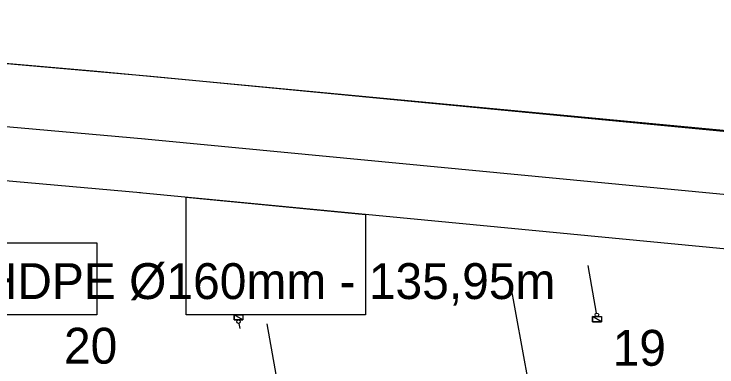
# Model space of a CAD drawing. Extents: x -263964 to -263544, y -1242317 to -1242020.
# Drawn here: x -263871.58 to -263832.36, y -1242081.29 to -1242061.62 of the extents above; entities that cross this region are included whole.
import ezdxf

# ---------------------------------------------------------------- set-up
doc = ezdxf.new("R2010")
doc.units = 0
for name, color, linetype in [('KFA_KOORDINACNA_SITUACIA_DSP_SEDA', 7, 'Continuous'), ('KFA_SO_50-2_POZIARNY_VODOVOD_BODY', 7, 'Continuous'), ('POPIS', 7, 'Continuous')]:
    doc.layers.add(name, color=color, linetype=linetype)

msp = doc.modelspace()

# ---------------------------------------------------------------- linework, layer by layer
at = {"layer": 'KFA_KOORDINACNA_SITUACIA_DSP_SEDA'}
for p, q in [((-263866.964, -1242064.823), (-263895.455, -1242062.322)), ((-263816.79, -1242069.539), (-263866.964, -1242064.823)), ((-263765.318, -1242074.565), (-263863.949, -1242065.106)), ((-263765.364, -1242078.076), (-263864.283, -1242068.59)), ((-263765.366, -1242081.09), (-263864.57, -1242071.577)), ((-263861.968, -1242078.382), (-263861.968, -1242071.826)), ((-263861.968, -1242071.826), (-263851.968, -1242072.785)), ((-263851.968, -1242072.785), (-263851.968, -1242078.382)), ((-263839.074, -1242078.29), (-263839.551, -1242075.646)), ((-263841.881, -1242087.633), (-263843.905, -1242076.433)), ((-263851.968, -1242078.382), (-263861.968, -1242078.382)), ((-263859.303, -1242078.673), (-263859.303, -1242078.383)), ((-263859.303, -1242078.383), (-263858.803, -1242078.383)), ((-263858.803, -1242078.673), (-263859.303, -1242078.383)), ((-263858.803, -1242078.673), (-263859.303, -1242078.383)), ((-263859.303, -1242078.383), (-263859.303, -1242078.673)), ((-263858.803, -1242078.383), (-263858.803, -1242078.673)), ((-263858.803, -1242078.673), (-263859.303, -1242078.673)), ((-263859.303, -1242078.673), (-263858.803, -1242078.673)), ((-263839.306, -1242078.779), (-263839.306, -1242078.489)), ((-263839.306, -1242078.489), (-263838.806, -1242078.489)), ((-263838.806, -1242078.779), (-263839.306, -1242078.489)), ((-263838.806, -1242078.779), (-263839.306, -1242078.489)), ((-263839.306, -1242078.489), (-263839.306, -1242078.779)), ((-263838.806, -1242078.779), (-263839.306, -1242078.779)), ((-263839.306, -1242078.779), (-263838.806, -1242078.779)), ((-263838.806, -1242078.489), (-263838.806, -1242078.779)), ((-263859.035, -1242078.872), (-263858.983, -1242079.157)), ((-263855.881, -1242087.633), (-263857.462, -1242078.882))]:
    msp.add_line(p, q, dxfattribs=at)
for points in [[(-263863.949, -1242065.106), (-263895.455, -1242062.322), (-263915.197, -1242060.921), (-263926.771, -1242063.254), (-263950.745, -1242062.149), (-263959.468, -1242059.534)], [(-263864.257, -1242068.593), (-263895.733, -1242065.811), (-263914.971, -1242064.445), (-263926.501, -1242066.77), (-263951.337, -1242065.625), (-263959.611, -1242063.145)], [(-263864.521, -1242071.581), (-263895.971, -1242068.802), (-263914.777, -1242067.467), (-263926.271, -1242069.784), (-263951.845, -1242068.605), (-263959.611, -1242066.277)]]:
    msp.add_lwpolyline(points, dxfattribs=at)
msp.add_lwpolyline([(-263881.968, -1242074.382), (-263866.968, -1242074.382), (-263866.968, -1242078.382), (-263881.968, -1242078.382)], close=True, dxfattribs=at)
for centre in [(-263839.056, -1242078.389), (-263859.053, -1242078.773)]:
    msp.add_circle(centre, 0.1, dxfattribs=at)

# ---------------------------------------------------------------- texts
at = {"layer": 'KFA_SO_50-2_POZIARNY_VODOVOD_BODY'}
for s, p in [('20', (-263868.793, -1242081.112)), ('19', (-263838.179, -1242081.229))]:
    msp.add_text(s, height=2, dxfattribs=at).set_placement(p)
at = {"layer": 'POPIS'}
msp.add_text('HDPE Ø160mm - 135,95m', height=2, dxfattribs=at).set_placement((-263873.329, -1242077.508))

doc.saveas('drawing.dxf')
